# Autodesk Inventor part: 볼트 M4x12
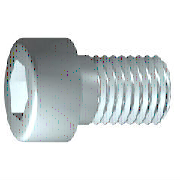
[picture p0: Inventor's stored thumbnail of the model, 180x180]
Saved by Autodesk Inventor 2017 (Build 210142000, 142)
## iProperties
IsCustomPart: 0
Created: 2012-02
Part Number: 볼트 M4x12
Material: 강철, 연강
Description: 6각 소켓 머리 캡 나사
Document SubType Name: Modeling
Standard: ISO 4762
Designer: mduedu
Standard Revision: Fourth edition 2004-03-01
Standards Organization: ISO
Language: ko-KR
Size Designation: M4 x 12
Categories: <MemberInstance><Categories><Category DisplayName="조임쇠" InternalName="e4da775c-781d-43d5-af7c-5136215cf5a6" Mnemonic="FSTN"><Category DisplayName="볼트" InternalN
Density: 7.75 g/cm^3
Appearance: 강철
Author: mduedu
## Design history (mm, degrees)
sketch "스케치1"
  geometry: L1 (-1, 0)-(12, 0); L2 (12, 0)-(12, 2); L3 (12, 2)-(1.75, 2); L4 (1.75, 2)-(1.32, 2); L5 (1.32, 2)-(0, 2); L6 (0, 2)-(0, 3.5); L7 (0, 3.5)-(-4, 3.5); L8 (-4, 3.5)-(-4, 1.732); L9 (-4, 1.732)-(-2, 1.732); L10 (-2, 1.732)-(-1, 0); L11 (-7.2, 0)-(15.2, 0) reference; L12 (0, -0.7)-(0, 4.2) reference; L13 (1.75, 2)-(0, 2)
  constraints: 22 end point, 6 parallel, 2 collinear, 2 perpendicular, 1 horizontal, 1 point on line
  dimensions: "d1" = 10.25 distance from line of L3.end L2 (= GEL); "d2" = 0.42952 distance of L4.end L3.end (computed from GAL); "d3" = 4 distance between parallel lines of L8 L6 (= KOH); "d4" = 2 distance of L8.end L9.end (= INTI); "d5" = 60 deg angle of L10 L1; "d6" = 4 diameter of L3 L1 (= GD); "d7" = 4 diameter of L5 L1 (= BDM); "d8" = 3.4641 diameter of L9 L1 (= 1.1547 x SW); "d9" = 7 diameter of L7 L1 (= KOD); "d26" = 12 distance between parallel lines of L12 L2 (= NLG)
revolve "본체" sketch "스케치1" stored, may be unused: angle "d10" = 90 deg
sketch "스케치2"
  geometry: L1 (0, -4.9)-(0, 4.9) reference; L2 (-4.9, 0)-(4.9, 0) reference; L3 (1.732, 0)-(0.866, -1.5); L4 (0.866, -1.5)-(-0.866, -1.5); L5 (-0.866, -1.5)-(-1.732, 0); L6 (-1.732, 0)-(-0.866, 1.5); L7 (-0.866, 1.5)-(0.866, 1.5); L8 (0.866, 1.5)-(1.732, 0); 2 further points
  constraints: 12 end point, 1 coincident, 1 horizontal alignment, 1 point on line, 12 other
extrude "슬롯" join sketch "스케치2" stored distance "d11" = 10; taper "d12" = 0 deg
workplane "Work Plane1"
fillet "Fillet2" dims "d30" = 0.1 (= R)
body "Solid1"
fillet "모깎기1" dims "d17" = 0.4 (= RR)
feature "스레드" dims "d13" = 10.25 (= GEL), "d14" = 0
chamfer "모따기1" distance "d15" = 0.42941 (= -0.5 x SPD + 0.5 x GD); stored, may be unused: second distance "d16" = 0.42941 (= GUL), angle "d27" = 45 deg
other parameters: "GD" = 4 [user parameter; used in 2 equation terms], "NLG" = 12 [user parameter; used in 1 equation term], "GEL" = 10.25 [user parameter; used in 2 equation terms], "KOD" = 7 [user parameter; used in 1 equation term], "KOH" = 4 [user parameter; used in 1 equation term], "INTI" = 2 [user parameter; used in 1 equation term], "GAL" = 0.42941 (= 0.61345 x PTC) [user parameter; used in 1 equation term], "GUL" = 0.42941 (= 0.61345 x PTC) [user parameter; used in 1 equation term], "BDM" = 4 (= NND) [user parameter; used in 1 equation term], "SW" = 3 [user parameter; used in 2 equation terms], "RR" = 0.4 [user parameter; used in 1 equation term], "SPD" = 3.14117 (= NND - 1.2269 x PTC) [user parameter; used in 1 equation term], "d19" = 0, "d28" = 0, "d29" = 0, "R" = 0.1 [user parameter; used in 1 equation term], "TOA" = 30 deg [user parameter], "GD1" = 3.14117 (= THREADDIA - 1.2269 x PTC) [user parameter], "THREADDIA" = 4 [user parameter; used in 1 equation term], "FAWI" = 45 deg [user parameter], "TPU" = 14.28571 (computed from PTC) [user parameter], "PTC" = 0.7 [user parameter; used in 5 equation terms], "NND" = 4 [user parameter; used in 2 equation terms], "E0" = 3.465 (= 1.155 x SW) [user parameter]
